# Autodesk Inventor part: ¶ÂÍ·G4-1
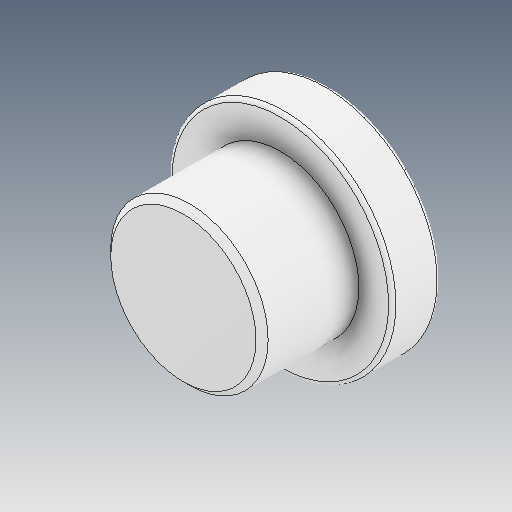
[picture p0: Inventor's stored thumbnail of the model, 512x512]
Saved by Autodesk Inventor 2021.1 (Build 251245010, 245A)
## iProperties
Created: 2021-05
Part Number: ¶ÂÍ·G4-1
Material: Ogólny
Document SubType Name: Modeling
Designer: user
Density: 1 g/cm^3
Appearance: Domyślna
Author: user
Revision Number: ÈÎºÎ
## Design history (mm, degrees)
feature "µ¹½Ç2"
node "Bryła1"
